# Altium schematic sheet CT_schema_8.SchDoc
size 251 x 159 mm
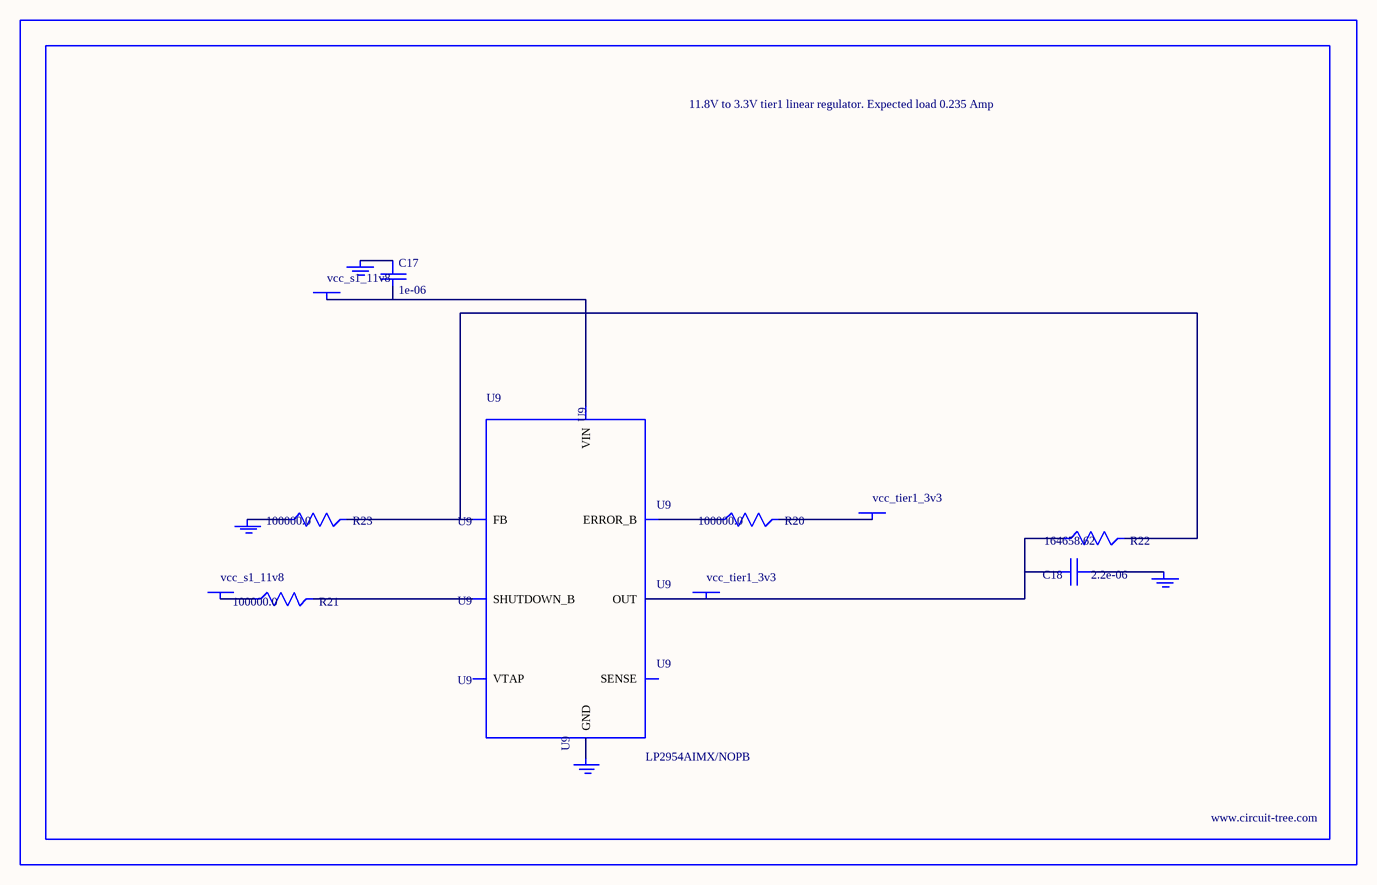
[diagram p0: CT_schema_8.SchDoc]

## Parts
BORDER7  (no value)
C17  1e-06  [EXV-9B]
C18  2.2e-06  [EXV-9B]
GND_INSTANCE_7_0  (no value)
GND_INSTANCE_7_1  (no value)
GND_INSTANCE_7_2  (no value)
GND_INSTANCE_7_3  (no value)
POWER_INSTANCE_7_0  vcc_s1_11v8
POWER_INSTANCE_7_1  vcc_tier1_3v3
POWER_INSTANCE_7_2  vcc_s1_11v8
POWER_INSTANCE_7_3  vcc_tier1_3v3
R20  100000.0  [R0603]
R21  100000.0  [R0603]
R22  164658.62  [R0603]
R23  100000.0  [R0603]
U9  LP2954AIMX/NOPB  [LP2954]

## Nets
NetC17_1: C17.1 GND_INSTANCE_7_2.0(GND)
NetC17_2: C17.2 POWER_INSTANCE_7_2.0(PWR) U9.8(VIN)
NetC18_1: C18.1 GND_INSTANCE_7_0.0(GND)
NetC18_2: C18.2 POWER_INSTANCE_7_3.0(PWR) R22.1 U9.1(OUT)
NetGND_INSTANCE_7_1_0: GND_INSTANCE_7_1.0(GND) R23.1
NetGND_INSTANCE_7_3_0: GND_INSTANCE_7_3.0(GND) U9.4(GND)
NetPOWER_INSTANCE_7_0_0: POWER_INSTANCE_7_0.0(PWR) R21.1
NetPOWER_INSTANCE_7_1_0: POWER_INSTANCE_7_1.0(PWR) R20.2
NetR20_1: R20.1 U9.5(ERROR_B)
NetR21_2: R21.2 U9.3(SHUTDOWN_B)
NetR22_2: R22.2 R23.2 U9.7(FB)

Not connected (* = marked no-connect by the designer): U9 2(SENSE) 6(VTAP)

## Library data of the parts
BORDER7 = BORDER_PAGE7
C17 = EDK105M050A9BAA
C18 = EDK225M050A9BAA
GND_INSTANCE_7_0-GND_INSTANCE_7_3 = GND
POWER_INSTANCE_7_0-POWER_INSTANCE_7_3 = PWR
R20 R21 R23 = RC0603JR-07100KL
R22 = R22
